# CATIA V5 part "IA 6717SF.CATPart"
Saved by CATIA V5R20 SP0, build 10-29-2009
Part number: IA 6717SF
Revision: ANY
Definition: UNKNOWN
Nomenclature: IA 6717SF
Source: Unknown
Bounding box of the stored display mesh (mm): x -3.35 to 3.35, y -7.95 to 9.02, z -3.186 to 3.186
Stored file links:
  C:\Users\Utente\Desktop\IO LAVORO\3D X SITO CF\CUMSA\3D files FA\FA 1267SF\IA 6717SF.CATPart

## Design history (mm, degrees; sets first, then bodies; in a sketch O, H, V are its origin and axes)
Body1 "Cortar-Extruir2" (main body)
  Solid1: solid without history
